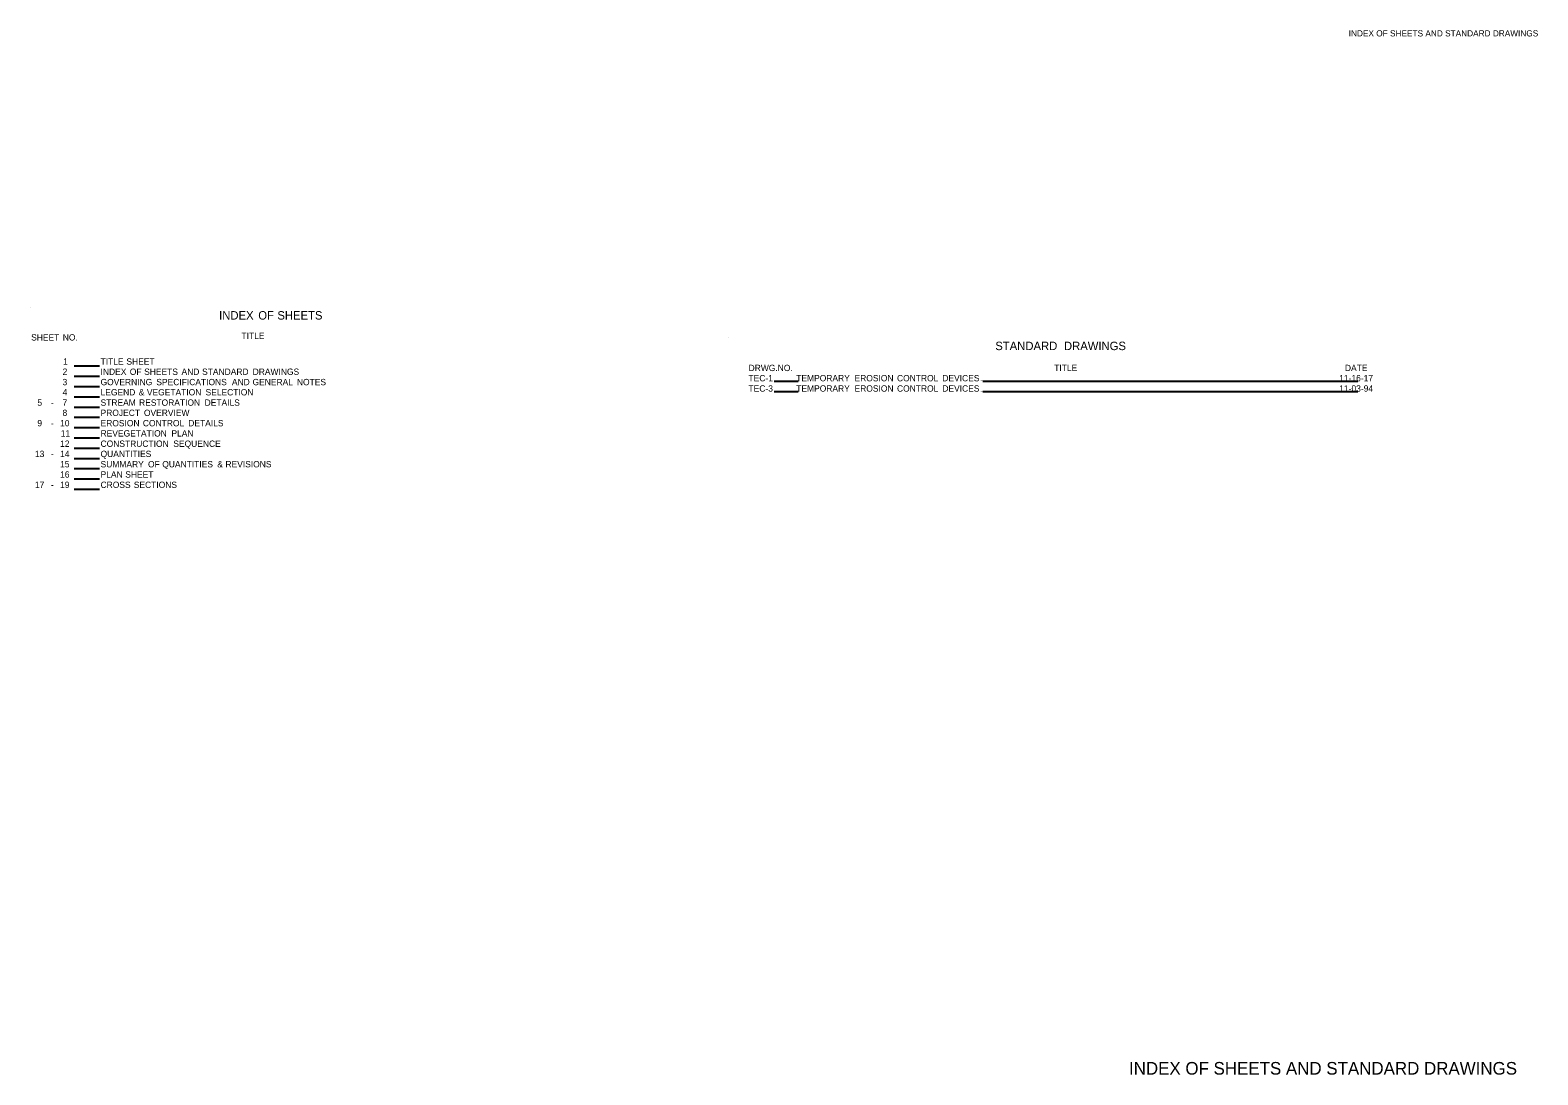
# Model space of a CAD drawing. Extents: x 1577333 to 26153757, y 723694 to 3772486.
import ezdxf

# ---------------------------------------------------------------- set-up
doc = ezdxf.new("R2010")
doc.units = 0
doc.layers.add('Default', color=7, linetype='Continuous')
doc.layers.add('R_Border', color=7, linetype='Continuous')

msp = doc.modelspace()

# ---------------------------------------------------------------- linework, layer by layer
at = {"layer": 'Default'}
for p, q in [((1577374.6, 724367.1), (1577398.5, 724367.1)), ((1577374.6, 724357.4), (1577398.5, 724357.4)), ((1577374.6, 724347.6), (1577398.5, 724347.6)), ((1578038.8, 724352.5), (1578061.4, 724352.5)), ((1578236.7, 724352.5), (1578592.7, 724352.5)), ((1577374.6, 724337.9), (1577398.5, 724337.9)), ((1578038.8, 724342.7), (1578061.4, 724342.7)), ((1578236.7, 724342.7), (1578592.7, 724342.7)), ((1577374.6, 724328.1), (1577398.5, 724328.1)), ((1577374.6, 724318.4), (1577398.5, 724318.4)), ((1577374.6, 724308.6), (1577398.5, 724308.6)), ((1577374.6, 724298.9), (1577398.5, 724298.9)), ((1577374.6, 724289.1), (1577398.5, 724289.1)), ((1577374.6, 724279.4), (1577398.5, 724279.4)), ((1577374.6, 724269.6), (1577398.5, 724269.6)), ((1577374.6, 724259.9), (1577398.5, 724259.9)), ((1577374.6, 724250.1), (1577398.5, 724250.1))]:
    msp.add_line(p, q, dxfattribs=at)
at = {"layer": 'R_Border'}
for p, q in [((1577332.7, 724422.7), (1577332.7, 724422.7)), ((1577995.4, 724393.7), (1577995.4, 724393.7))]:
    msp.add_line(p, q, dxfattribs=at)

# ---------------------------------------------------------------- texts
at = {"layer": 'Default'}
for s, height, p in [('INDEX', 8, (1577512, 724411.1)), (' OF', 8, (1577546.2, 724411.1)), (' SHEETS', 8, (1577564.3, 724411.1)), ('SHEET', 6, (1577333.6, 724391.2)), (' NO.', 6, (1577361.4, 724391.2)), ('                                                            TITLE', 6, (1577399.5, 724392.6)), ('STANDARD', 8, (1578248.6, 724382.1)), (' DRAWINGS', 8, (1578310.8, 724382.1)), ('2', 6, (1577363.5, 724358.6)), ('1', 6, (1577364, 724368.3)), ('TITLE', 6, (1577399.5, 724368.3)), ('INDEX', 6, (1577399.5, 724358.6)), (' SHEET', 6, (1577421.8, 724368.3)), (' OF', 6, (1577425, 724358.6)), (' SHEETS', 6, (1577438.6, 724358.6)), (' AND', 6, (1577474.1, 724358.6)), (' STANDARD', 6, (1577493.6, 724358.6)), (' DRAWINGS', 6, (1577541.6, 724358.6)), ('DRWG.NO.', 6, (1578014.5, 724362.2)), ('TITLE', 6, (1578304.5, 724362.2)), ('DATE', 6, (1578580.4, 724362.2)), ('3', 6, (1577363.4, 724348.8)), ('GOVERNING', 6, (1577399.5, 724348.8)), (' SPECIFICATIONS', 6, (1577450.2, 724348.8)), (' AND', 6, (1577521.9, 724348.8)), (' GENERAL', 6, (1577541.5, 724348.8)), (' NOTES', 6, (1577583.6, 724348.8)), ('TEC-1', 6, (1578014.4, 724352.5)), ('TEC-3', 6, (1578014.4, 724342.7)), ('TEMPORARY', 6, (1578059.7, 724352.5)), ('TEMPORARY', 6, (1578059.7, 724342.7)), (' EROSION', 6, (1578112.8, 724352.5)), (' EROSION', 6, (1578112.8, 724342.7)), (' CONTROL', 6, (1578153.1, 724352.5)), (' CONTROL', 6, (1578153.1, 724342.7)), (' DEVICES', 6, (1578196.1, 724352.5)), (' DEVICES', 6, (1578196.1, 724342.7)), ('____________________________________', 4.5, (1578234.8, 724354)), ('11-16-17', 6, (1578575, 724352.5)), ('11-03-94', 6, (1578575, 724342.7)), ('5', 6, (1577339.5, 724329.3)), ('4', 6, (1577363.5, 724339.1)), ('7', 6, (1577363.4, 724329.3)), ('STREAM', 6, (1577399.5, 724329.3)), ('LEGEND', 6, (1577399.5, 724339.1)), (' &', 6, (1577433.5, 724339.1)), (' RESTORATION', 6, (1577433.8, 724329.3)), (' VEGETATION', 6, (1577441.2, 724339.1)), (' DETAILS', 6, (1577496, 724329.3)), (' SELECTION', 6, (1577496.9, 724339.1)), ('___________________________________________________________', 4.5, (1578234.8, 724344.2)), ('-', 6, (1577352.4, 724329.3)), ('8', 6, (1577363.4, 724319.6)), ('PROJECT', 6, (1577399.5, 724319.6)), (' OVERVIEW', 6, (1577438.4, 724319.6)), ('9', 6, (1577339.5, 724309.8)), ('-', 6, (1577352.4, 724309.8)), ('10', 6, (1577361.1, 724309.8)), ('11', 6, (1577361.7, 724300.1)), ('EROSION', 6, (1577399.5, 724309.8)), ('REVEGETATION', 6, (1577399.5, 724300.1)), (' CONTROL', 6, (1577437.4, 724309.8)), (' PLAN', 6, (1577464.5, 724300.1)), (' DETAILS', 6, (1577480.5, 724309.8)), ('12', 6, (1577361.1, 724290.3)), ('CONSTRUCTION', 6, (1577399.5, 724290.3)), (' SEQUENCE', 6, (1577466.3, 724290.3)), ('13', 6, (1577337.2, 724280.6)), ('-', 6, (1577352.4, 724280.6)), ('14', 6, (1577361.1, 724280.6)), ('15', 6, (1577361.1, 724270.8)), ('QUANTITIES', 6, (1577399.5, 724280.6)), ('SUMMARY', 6, (1577399.5, 724270.8)), (' OF', 6, (1577442.3, 724270.8)), (' QUANTITIES', 6, (1577455.8, 724270.8)), (' &', 6, (1577508, 724270.8)), (' REVISIONS', 6, (1577515.8, 724270.8)), ('16', 6, (1577361.1, 724261.1)), ('PLAN', 6, (1577399.5, 724261.1)), (' SHEET', 6, (1577420.7, 724261.1)), ('17', 6, (1577337.2, 724251.3)), ('-', 6, (1577352.4, 724251.3)), ('19', 6, (1577361.1, 724251.3)), ('CROSS', 6, (1577399.5, 724251.3)), (' SECTIONS', 6, (1577428.8, 724251.3))]:
    msp.add_text(s, height=height, dxfattribs=at).set_placement(p)
at = {"layer": 'R_Border'}
for height, p in [(5.862, (1578584, 724679.8)), (12, (1578375.5, 723694.5))]:
    msp.add_text('INDEX OF SHEETS AND STANDARD DRAWINGS', height=height, dxfattribs=at).set_placement(p)

doc.saveas('drawing.dxf')
